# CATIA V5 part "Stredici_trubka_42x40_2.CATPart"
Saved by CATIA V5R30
Part number: Stredici_trubka_42x40_2
Definition: E 1160_42x40_1
Nomenclature: E 1160_42x40_1
Source: Unknown
Description: PART--DESC
Bounding box of the stored display mesh (mm): x 166 to 208, y 116.01 to 157.99, z 90.7 to 130.7
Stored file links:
  E:\Bakalarka\Model\Forma_v7\Stredici_trubka_42x40_2.CATPart
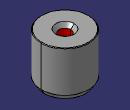
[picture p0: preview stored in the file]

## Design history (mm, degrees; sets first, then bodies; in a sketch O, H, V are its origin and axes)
Body1 "MANIFOLD_SOLID_BREP #3866" (main body)
  Solid1: solid without history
